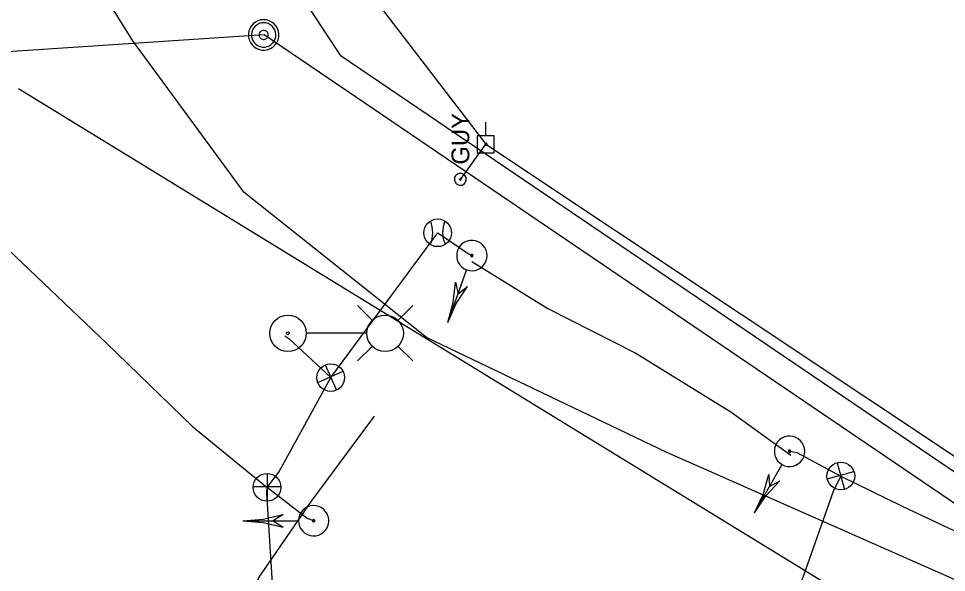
# Model space of a CAD drawing. Extents: x 600849 to 606371, y 330010 to 403088.
# Drawn here: x 602663.8 to 602865.1, y 353571.8 to 353691.9 of the extents above; entities that cross this region are included whole.
import ezdxf

# ---------------------------------------------------------------- set-up
doc = ezdxf.new("R2010")
doc.units = 0
for name, color, linetype in [('E_LTG', 7, 'Continuous'), ('E_LTG_CID', 7, 'Continuous'), ('E_SIG', 7, 'Continuous'), ('E_UTL_E_UG', 7, 'Continuous'), ('E_UTL_EGuyWire', 7, 'Continuous'), ('E_UTL_EPowerPole', 7, 'Continuous'), ('E_UTL_G_UG', 7, 'Continuous'), ('E_UTL_Overhead', 7, 'Continuous'), ('E_UTL_SAN', 7, 'Continuous'), ('E_UTL_SAN_UG_MMSD', 7, 'Continuous'), ('E_UTL_T_UG', 7, 'Continuous')]:
    doc.layers.add(name, color=color, linetype=linetype)

# ---------------------------------------------------------------- blocks, each defined once
blk = doc.blocks.new('_U290')
at = {"layer": 'E_SIG'}
for p, q in [((0, 6.1), (0, -6.1)), ((-6.09, 0.4), (6.1, 0.4))]:
    blk.add_line(p, q, dxfattribs=at)
blk.add_circle((0, 0.01), 6.1, dxfattribs=at)
blk = doc.blocks.new('_U291')
at = {"layer": 'E_SIG'}
blk.add_circle((0, 0.01), 6.1, dxfattribs=at)
for centre, start, end in [((-15.45, 0.12), 336.6741, 22.5272), ((15.46, 0.15), 157.5751, 203.4282)]:
    blk.add_arc(centre, 13.28, start, end, dxfattribs=at)
blk = doc.blocks.new('_U292')
at = {"layer": 'E_SIG'}
for p, q in [((0, 6.1), (0, -6.1)), ((-6.09, 0.4), (6.1, 0.4))]:
    blk.add_line(p, q, dxfattribs=at)
blk.add_circle((0, 0.01), 6.1, dxfattribs=at)
blk = doc.blocks.new('_U293')
at = {"layer": 'E_SIG'}
for p, q in [((0, 6.1), (0, -6.1)), ((-6.09, 0.4), (6.1, 0.4))]:
    blk.add_line(p, q, dxfattribs=at)
blk.add_circle((0, 0.01), 6.1, dxfattribs=at)

msp = doc.modelspace()

# ---------------------------------------------------------------- linework, layer by layer
at = {"layer": 'E_LTG'}
for points in [[(602740.56, 353626.47), (602737.33, 353629.7)], [(602746.1, 353626.47), (602749.33, 353629.7)], [(602739.3, 353623.7), (602726.25, 353623.7)], [(602740.56, 353620.93), (602737.33, 353617.7)], [(602746.1, 353620.93), (602749.33, 353617.7)]]:
    msp.add_lwpolyline(points, dxfattribs=at)
for centre, radius in [((602722.23, 353623.7), 3.96), ((602743.32, 353623.7), 3.96), ((602722.23, 353623.7), 0.303)]:
    msp.add_circle(centre, radius, dxfattribs=at)
at = {"layer": 'E_LTG_CID'}
msp.add_lwpolyline([(602721.55, 353623.12), (602722.41, 353622.6), (602731.52, 353614.09)], dxfattribs=at)
at = {"layer": 'E_SIG'}
for points in [[(602571.72, 353774.84), (602571.97, 353773.77), (602590.27, 353736.74), (602605.34, 353711.08), (602623.14, 353684.38), (602630.1, 353677.26), (602640.77, 353664.51), (602660.07, 353643.26), (602682.9, 353621.55), (602701.56, 353603.51), (602717.69, 353590.29)], [(602731.52, 353614.09), (602754.72, 353645.48), (602761.53, 353640.88), (602762.12, 353640.55)], [(602761.01, 353637.44), (602761.61, 353637.29), (602762.24, 353637.25), (602762.86, 353637.33), (602763.46, 353637.53), (602764, 353637.84), (602764.48, 353638.24), (602764.88, 353638.73), (602765.17, 353639.28), (602765.36, 353639.88), (602765.42, 353640.51), (602765.37, 353641.13), (602765.2, 353641.74), (602764.92, 353642.3), (602764.54, 353642.8), (602764.07, 353643.21), (602763.53, 353643.53), (602762.94, 353643.75), (602762.32, 353643.84), (602761.69, 353643.82), (602761.08, 353643.68), (602760.51, 353643.43), (602759.99, 353643.07), (602759.55, 353642.62), (602759.21, 353642.1), (602758.97, 353641.52), (602758.84, 353640.9), (602758.84, 353640.27), (602758.95, 353639.66), (602759.17, 353639.07), (602759.5, 353638.54), (602759.93, 353638.08), (602760.44, 353637.71), (602761.01, 353637.44)], [(602762.04, 353640.31), (602762.08, 353640.3), (602762.13, 353640.3), (602762.18, 353640.3), (602762.23, 353640.32), (602762.27, 353640.34), (602762.3, 353640.37), (602762.33, 353640.41), (602762.36, 353640.45), (602762.37, 353640.5), (602762.38, 353640.55), (602762.37, 353640.59), (602762.36, 353640.64), (602762.34, 353640.68), (602762.31, 353640.72), (602762.27, 353640.75), (602762.23, 353640.78), (602762.19, 353640.79), (602762.14, 353640.8), (602762.09, 353640.8), (602762.04, 353640.79), (602762, 353640.77), (602761.96, 353640.74), (602761.93, 353640.71), (602761.9, 353640.67), (602761.88, 353640.62), (602761.87, 353640.58), (602761.87, 353640.53), (602761.88, 353640.48), (602761.9, 353640.44), (602761.92, 353640.39), (602761.96, 353640.36), (602761.99, 353640.33), (602762.04, 353640.31)], [(602756.91, 353626.06), (602760.99, 353637.39)], [(602762.13, 353639.29), (602778.6, 353629.08), (602797.67, 353619.36), (602818.28, 353606.66), (602831.3, 353597.25)], [(602756.91, 353626.06), (602758.09, 353630.37), (602758.59, 353634.8)], [(602756.91, 353626.06), (602758.74, 353630.13), (602761.18, 353633.87)], [(602758.6, 353634.8), (602759.14, 353632.27)], [(602759.14, 353632.27), (602761.18, 353633.87)], [(602709.87, 353549.93), (602711, 353551.67), (602713.58, 353553.73), (602719.17, 353564.85), (602717.63, 353589.05), (602717.69, 353590.29), (602720.25, 353593.61), (602731.52, 353614.09)], [(602829.42, 353595.24), (602829.99, 353594.99), (602830.6, 353594.84), (602831.23, 353594.81), (602831.85, 353594.91), (602832.44, 353595.11), (602832.98, 353595.43), (602833.46, 353595.84), (602833.84, 353596.34), (602834.12, 353596.9), (602834.3, 353597.5), (602834.35, 353598.13), (602834.29, 353598.75), (602834.11, 353599.35), (602833.82, 353599.91), (602833.43, 353600.4), (602832.95, 353600.81), (602832.41, 353601.12), (602831.82, 353601.32), (602831.19, 353601.41), (602830.57, 353601.37), (602829.96, 353601.22), (602829.39, 353600.96), (602828.88, 353600.59), (602828.45, 353600.14), (602828.11, 353599.61), (602827.88, 353599.02), (602827.77, 353598.41), (602827.77, 353597.78), (602827.89, 353597.16), (602828.13, 353596.58), (602828.47, 353596.06), (602828.91, 353595.6), (602829.42, 353595.24)], [(602830.93, 353597.89), (602830.97, 353597.87), (602831.02, 353597.86), (602831.07, 353597.86), (602831.12, 353597.86), (602831.16, 353597.88), (602831.2, 353597.9), (602831.24, 353597.94), (602831.27, 353597.97), (602831.29, 353598.02), (602831.3, 353598.06), (602831.31, 353598.11), (602831.3, 353598.16), (602831.29, 353598.2), (602831.27, 353598.25), (602831.24, 353598.28), (602831.2, 353598.32), (602831.16, 353598.34), (602831.11, 353598.35), (602831.07, 353598.36), (602831.02, 353598.36), (602830.97, 353598.35), (602830.93, 353598.33), (602830.89, 353598.3), (602830.86, 353598.26), (602830.83, 353598.22), (602830.81, 353598.18), (602830.8, 353598.13), (602830.8, 353598.08), (602830.81, 353598.04), (602830.83, 353597.99), (602830.86, 353597.95), (602830.89, 353597.92), (602830.93, 353597.89)], [(602831.06, 353598.11), (602832.65, 353597.81), (602842.18, 353592.74)], [(602823.43, 353584.73), (602829.39, 353595.19)], [(602823.43, 353584.73), (602825.33, 353588.77), (602826.59, 353593.06)], [(602826.59, 353593.06), (602826.69, 353590.46)], [(602823.43, 353584.73), (602825.93, 353588.43), (602828.98, 353591.69)], [(602826.69, 353590.46), (602828.98, 353591.69)], [(602829.52, 353555.99), (602829.37, 353557), (602830.25, 353560.21), (602840.58, 353589.43), (602842.18, 353592.74)], [(602842.18, 353592.74), (602855.51, 353586.22), (602870.41, 353579.21), (602935.32, 353551.14), (602993.08, 353516.29)], [(602727.82, 353583.04), (602726.39, 353583.52), (602717.69, 353590.29)], [(602724.52, 353583.04), (602724.58, 353582.42), (602724.76, 353581.82), (602725.04, 353581.26), (602725.43, 353580.77), (602725.9, 353580.35), (602726.45, 353580.04), (602727.04, 353579.84), (602727.66, 353579.75), (602728.29, 353579.78), (602728.9, 353579.92), (602729.47, 353580.18), (602729.98, 353580.55), (602730.41, 353581), (602730.75, 353581.53), (602730.99, 353582.11), (602731.1, 353582.73), (602731.1, 353583.36), (602730.99, 353583.97), (602730.75, 353584.55), (602730.41, 353585.08), (602729.98, 353585.54), (602729.47, 353585.9), (602728.9, 353586.16), (602728.29, 353586.31), (602727.66, 353586.34), (602727.04, 353586.25), (602726.45, 353586.04), (602725.9, 353585.73), (602725.43, 353585.32), (602725.04, 353584.83), (602724.76, 353584.27), (602724.58, 353583.67), (602724.52, 353583.04)], [(602712.42, 353583.04), (602716.87, 353583.39), (602721.22, 353584.42)], [(602712.42, 353583.04), (602724.46, 353583.04)], [(602712.42, 353583.04), (602716.87, 353582.7), (602721.22, 353581.67)], [(602721.22, 353584.42), (602719.02, 353583.04)], [(602719.02, 353583.04), (602721.22, 353581.67)], [(602727.57, 353583.04), (602727.57, 353582.99), (602727.58, 353582.95), (602727.61, 353582.91), (602727.64, 353582.87), (602727.67, 353582.84), (602727.71, 353582.81), (602727.76, 353582.8), (602727.81, 353582.79), (602727.85, 353582.79), (602727.9, 353582.8), (602727.94, 353582.82), (602727.98, 353582.85), (602728.02, 353582.89), (602728.04, 353582.93), (602728.06, 353582.97), (602728.07, 353583.02), (602728.07, 353583.07), (602728.06, 353583.11), (602728.04, 353583.16), (602728.02, 353583.2), (602727.98, 353583.23), (602727.94, 353583.26), (602727.9, 353583.28), (602727.85, 353583.29), (602727.81, 353583.29), (602727.76, 353583.29), (602727.71, 353583.27), (602727.67, 353583.25), (602727.64, 353583.22), (602727.61, 353583.18), (602727.58, 353583.14), (602727.57, 353583.09), (602727.57, 353583.04)]]:
    msp.add_lwpolyline(points, dxfattribs=at)
at = {"layer": 'E_UTL_E_UG'}
msp.add_lwpolyline([(602709.87, 353549.93), (602709.28, 353553.69), (602709.91, 353558.18), (602715.96, 353570.79), (602727.31, 353587.28), (602741.01, 353605.74)], dxfattribs=at)
at = {"layer": 'E_UTL_EGuyWire'}
msp.add_line((602759.64, 353657.08), (602765.19, 353664.71), dxfattribs=at)
for points in [[(602759.64, 353658.37), (602759.4, 353658.34), (602759.16, 353658.27), (602758.95, 353658.16), (602758.75, 353658.01), (602758.6, 353657.83), (602758.47, 353657.61), (602758.39, 353657.38), (602758.36, 353657.14), (602758.37, 353656.9), (602758.43, 353656.66), (602758.53, 353656.44), (602758.67, 353656.24), (602758.85, 353656.07), (602759.05, 353655.94), (602759.28, 353655.85), (602759.52, 353655.8), (602759.76, 353655.8), (602760, 353655.85), (602760.23, 353655.94), (602760.43, 353656.07), (602760.61, 353656.24), (602760.75, 353656.44), (602760.85, 353656.66), (602760.91, 353656.9), (602760.92, 353657.14), (602760.89, 353657.38), (602760.81, 353657.61), (602760.69, 353657.83), (602760.53, 353658.01), (602760.33, 353658.16), (602760.12, 353658.27), (602759.88, 353658.34), (602759.64, 353658.37)], [(602759.64, 353657.24), (602759.61, 353657.24), (602759.58, 353657.23), (602759.55, 353657.22), (602759.53, 353657.2), (602759.51, 353657.17), (602759.49, 353657.15), (602759.48, 353657.12), (602759.48, 353657.09), (602759.48, 353657.06), (602759.49, 353657.03), (602759.5, 353657), (602759.52, 353656.98), (602759.54, 353656.96), (602759.57, 353656.94), (602759.6, 353656.93), (602759.63, 353656.92), (602759.66, 353656.92), (602759.69, 353656.93), (602759.71, 353656.94), (602759.74, 353656.96), (602759.76, 353656.98), (602759.78, 353657), (602759.79, 353657.03), (602759.8, 353657.06), (602759.8, 353657.09), (602759.8, 353657.12), (602759.79, 353657.15), (602759.77, 353657.17), (602759.75, 353657.2), (602759.73, 353657.22), (602759.7, 353657.23), (602759.67, 353657.24), (602759.64, 353657.24)]]:
    msp.add_lwpolyline(points, dxfattribs=at)
at = {"layer": 'E_UTL_EPowerPole'}
for points in [[(602765.16, 353666.55), (602765.16, 353669.46)], [(602767, 353666.55), (602763.31, 353666.55)], [(602763.31, 353666.55), (602763.31, 353662.86)], [(602767, 353662.86), (602767, 353666.55)], [(602765.43, 353664.71), (602765.42, 353664.76), (602765.41, 353664.8), (602765.39, 353664.84), (602765.36, 353664.88), (602765.33, 353664.9), (602765.29, 353664.93), (602765.24, 353664.94), (602765.2, 353664.95), (602765.15, 353664.95), (602765.11, 353664.94), (602765.07, 353664.92), (602765.03, 353664.89), (602765, 353664.86), (602764.98, 353664.82), (602764.96, 353664.78), (602764.95, 353664.73), (602764.95, 353664.69), (602764.96, 353664.64), (602764.98, 353664.6), (602765, 353664.56), (602765.03, 353664.53), (602765.07, 353664.5), (602765.11, 353664.49), (602765.15, 353664.47), (602765.2, 353664.47), (602765.24, 353664.48), (602765.29, 353664.49), (602765.33, 353664.52), (602765.36, 353664.55), (602765.39, 353664.58), (602765.41, 353664.62), (602765.42, 353664.67), (602765.43, 353664.71)], [(602763.31, 353662.86), (602767, 353662.86)]]:
    msp.add_lwpolyline(points, dxfattribs=at)
at = {"layer": 'E_UTL_G_UG'}
msp.add_line((602873.06, 353589.33), (602733.76, 353683.78), dxfattribs=at)
for points in [[(602733.76, 353683.78), (602567.33, 353935.25)], [(602986.31, 353574.37), (602934.58, 353510.81), (602663.79, 353676.69)]]:
    msp.add_lwpolyline(points, dxfattribs=at)
at = {"layer": 'E_UTL_Overhead'}
msp.add_lwpolyline([(602664.33, 353794.06), (602714.7, 353730.52), (602765.19, 353664.71), (602931.16, 353554.23)], dxfattribs=at)
at = {"layer": 'E_UTL_SAN'}
for points in [[(602716.96, 353691.7), (602716.33, 353691.64), (602715.73, 353691.46), (602715.18, 353691.17), (602714.68, 353690.79), (602714.27, 353690.31), (602713.96, 353689.77), (602713.75, 353689.18), (602713.66, 353688.56), (602713.69, 353687.93), (602713.84, 353687.32), (602714.1, 353686.75), (602714.47, 353686.24), (602714.92, 353685.8), (602715.45, 353685.47), (602716.03, 353685.23), (602716.65, 353685.11), (602717.27, 353685.11), (602717.89, 353685.23), (602718.47, 353685.47), (602719, 353685.8), (602719.45, 353686.24), (602719.82, 353686.75), (602720.08, 353687.32), (602720.23, 353687.93), (602720.26, 353688.56), (602720.17, 353689.18), (602719.96, 353689.77), (602719.65, 353690.31), (602719.24, 353690.79), (602718.74, 353691.17), (602718.19, 353691.46), (602717.58, 353691.64), (602716.96, 353691.7)], [(602716.96, 353691.04), (602716.46, 353690.99), (602715.98, 353690.85), (602715.53, 353690.62), (602715.14, 353690.31), (602714.81, 353689.93), (602714.56, 353689.49), (602714.39, 353689.02), (602714.32, 353688.52), (602714.35, 353688.02), (602714.46, 353687.53), (602714.67, 353687.08), (602714.96, 353686.67), (602715.33, 353686.32), (602715.75, 353686.05), (602716.22, 353685.87), (602716.71, 353685.77), (602717.21, 353685.77), (602717.7, 353685.87), (602718.17, 353686.05), (602718.59, 353686.32), (602718.95, 353686.67), (602719.25, 353687.08), (602719.45, 353687.53), (602719.57, 353688.02), (602719.6, 353688.52), (602719.53, 353689.02), (602719.36, 353689.49), (602719.11, 353689.93), (602718.78, 353690.31), (602718.39, 353690.62), (602717.94, 353690.85), (602717.46, 353690.99), (602716.96, 353691.04)], [(602716.96, 353689.39), (602716.77, 353689.37), (602716.59, 353689.32), (602716.42, 353689.23), (602716.28, 353689.11), (602716.15, 353688.97), (602716.06, 353688.81), (602716, 353688.63), (602715.97, 353688.45), (602715.98, 353688.26), (602716.02, 353688.07), (602716.1, 353687.9), (602716.21, 353687.75), (602716.35, 353687.62), (602716.51, 353687.52), (602716.68, 353687.45), (602716.87, 353687.41), (602717.05, 353687.41), (602717.24, 353687.45), (602717.41, 353687.52), (602717.57, 353687.62), (602717.71, 353687.75), (602717.82, 353687.9), (602717.89, 353688.07), (602717.94, 353688.26), (602717.95, 353688.45), (602717.92, 353688.63), (602717.86, 353688.81), (602717.77, 353688.97), (602717.64, 353689.11), (602717.49, 353689.23), (602717.33, 353689.32), (602717.15, 353689.37), (602716.96, 353689.39)]]:
    msp.add_lwpolyline(points, dxfattribs=at)
at = {"layer": 'E_UTL_SAN_UG_MMSD'}
for p, q in [((602400.64, 353667.45), (602717.07, 353688.47)), ((602717.07, 353688.47), (602941.55, 353536.12))]:
    msp.add_line(p, q, dxfattribs=at)
at = {"layer": 'E_UTL_T_UG'}
msp.add_lwpolyline([(602887.83, 353560.35), (602867.01, 353570.21), (602804.28, 353597.95), (602752.29, 353622.75), (602712.74, 353654.2), (602688.6, 353687.1), (602664.91, 353725.04), (602630.3, 353786.96), (602600.91, 353850.51), (602568.77, 353931.2)], dxfattribs=at)

# ---------------------------------------------------------------- block references
at = {"layer": 'E_SIG', "xscale": 0.49212500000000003, "yscale": 0.49212500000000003}
for name, p in [('_U291', (602754.72, 353645.48)), ('_U292', (602717.69, 353590.29))]:
    msp.add_blockref(name, p, dxfattribs=at)
at = {"layer": 'E_SIG', "yscale": 0.49212500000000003}
for name, p, xscale, rotation in [('_U290', (602731.52, 353614.09), 0.492125, 23.96109937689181), ('_U293', (602842.18, 353592.74), 0.49212500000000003, 15.270282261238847)]:
    msp.add_blockref(name, p, dxfattribs=dict(at, xscale=xscale, rotation=rotation))

# ---------------------------------------------------------------- texts
at = {"layer": 'E_UTL_EGuyWire'}
msp.add_text('GUY', height=3.85, rotation=90, dxfattribs=at).set_placement((602761.57, 353660.29))

doc.saveas('drawing.dxf')
